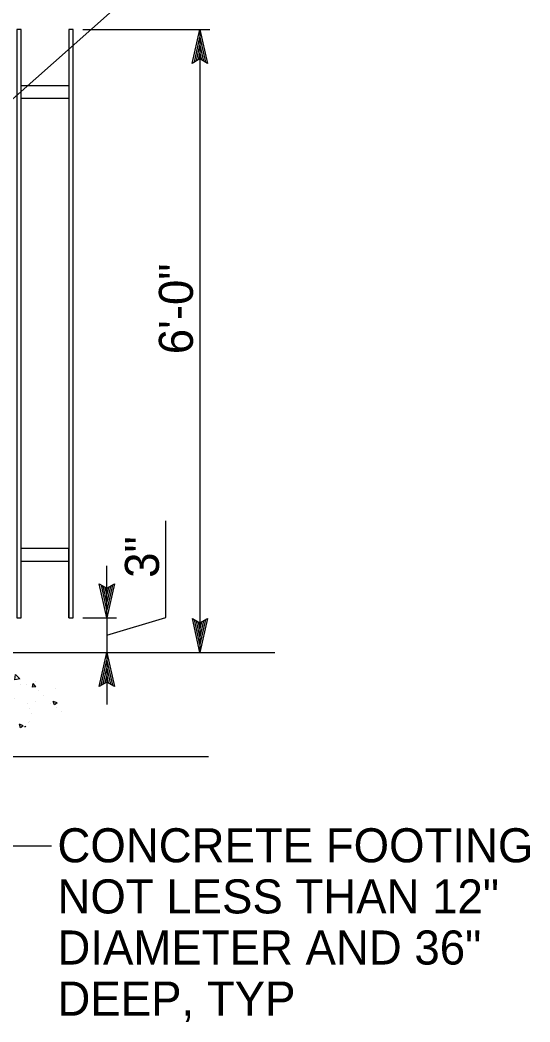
# Model space of a CAD drawing. Extents: x -123486 to -116575, y -107066 to -101122.
# Drawn here: x -118413.2 to -118323.4, y -103122.8 to -102946.3 of the extents above; entities that cross this region are included whole.
import ezdxf

# ---------------------------------------------------------------- set-up
doc = ezdxf.new("R2010")
doc.units = 0
for name, color, linetype in [('Erosion C (Lv35)', 7, 'Continuous'), ('G-MARK', 7, 'Continuous'), ('Misc CnstDet(22)', 7, 'Continuous')]:
    doc.layers.add(name, color=color, linetype=linetype)

# ---------------------------------------------------------------- blocks, each defined once
blk = doc.blocks.new('SC8415')
at = {"layer": 'Erosion C (Lv35)'}
for p, q in [((-1.69606, 1.76963), (-1.69579, 1.76945)), ((-1.69579, 1.76945), (-1.69573, 1.76963)), ((-1.70669, 1.76754), (-1.7059, 1.76836)), ((-1.70579, 1.7674), (-1.7059, 1.76836)), ((-1.70304, 1.76795), (-1.70304, 1.76795)), ((-1.6975, 1.7679), (-1.6975, 1.7679)), ((-1.69662, 1.7688), (-1.69662, 1.7688)), ((-1.69408, 1.76913), (-1.69408, 1.76913)), ((-1.69228, 1.76861), (-1.69228, 1.76861)), ((-1.68716, 1.76862), (-1.68716, 1.76862)), ((-1.68715, 1.76926), (-1.68715, 1.76926)), ((-1.70955, 1.76614), (-1.70906, 1.76672)), ((-1.70955, 1.76614), (-1.70894, 1.76608)), ((-1.70943, 1.76711), (-1.70943, 1.76711)), ((-1.70894, 1.76609), (-1.70906, 1.76672)), ((-1.70791, 1.76649), (-1.70791, 1.76649)), ((-1.70689, 1.76745), (-1.70689, 1.76745)), ((-1.70672, 1.76656), (-1.70672, 1.76656)), ((-1.70669, 1.76754), (-1.70579, 1.7674)), ((-1.70484, 1.76651), (-1.70412, 1.76679)), ((-1.70484, 1.76651), (-1.70433, 1.76617)), ((-1.70433, 1.76617), (-1.70412, 1.76679)), ((-1.70278, 1.76714), (-1.70278, 1.76714)), ((-1.70226, 1.7655), (-1.70177, 1.76608)), ((-1.70165, 1.76545), (-1.70177, 1.76609)), ((-1.7013, 1.76633), (-1.7013, 1.76633)), ((-1.69901, 1.76659), (-1.69901, 1.76659)), ((-1.69588, 1.7661), (-1.69588, 1.7661)), ((-1.69585, 1.76586), (-1.69506, 1.76668)), ((-1.69494, 1.76572), (-1.69506, 1.76668)), ((-1.69309, 1.7676), (-1.69309, 1.7676)), ((-1.69023, 1.7657), (-1.68952, 1.76597)), ((-1.68973, 1.76536), (-1.68952, 1.76597)), ((-1.68649, 1.76648), (-1.68649, 1.76648)), ((-1.68473, 1.76639), (-1.68473, 1.76639)), ((-1.68394, 1.76681), (-1.68394, 1.76681)), ((-1.682, 1.76664), (-1.682, 1.76664)), ((-1.71312, 1.76577), (-1.71312, 1.76577)), ((-1.71086, 1.76455), (-1.71086, 1.76455)), ((-1.71, 1.76543), (-1.71, 1.76543)), ((-1.70494, 1.76557), (-1.70494, 1.76557)), ((-1.70458, 1.7652), (-1.70458, 1.7652)), ((-1.70226, 1.7655), (-1.70165, 1.76545)), ((-1.6993, 1.76479), (-1.6993, 1.76479)), ((-1.69916, 1.76497), (-1.69916, 1.76497)), ((-1.69762, 1.76452), (-1.69762, 1.76452)), ((-1.69675, 1.76513), (-1.69675, 1.76513)), ((-1.69658, 1.76435), (-1.69658, 1.76435)), ((-1.69585, 1.76586), (-1.69494, 1.76572)), ((-1.69497, 1.76486), (-1.69449, 1.76545)), ((-1.69497, 1.76486), (-1.69437, 1.76481)), ((-1.69437, 1.76481), (-1.69448, 1.76545)), ((-1.69373, 1.76474), (-1.69373, 1.76474)), ((-1.6929, 1.76563), (-1.6929, 1.76563)), ((-1.69241, 1.76523), (-1.69241, 1.76523)), ((-1.69065, 1.76537), (-1.69065, 1.76537)), ((-1.69045, 1.76587), (-1.69045, 1.76587)), ((-1.69023, 1.7657), (-1.68973, 1.76536)), ((-1.68831, 1.76451), (-1.68831, 1.76451)), ((-1.68769, 1.76423), (-1.6872, 1.76481)), ((-1.68769, 1.76423), (-1.68708, 1.76417)), ((-1.68727, 1.76588), (-1.68727, 1.76588)), ((-1.68708, 1.76417), (-1.6872, 1.76481)), ((-1.68503, 1.76565), (-1.68503, 1.76565)), ((-1.685, 1.76418), (-1.68421, 1.765)), ((-1.685, 1.76418), (-1.6841, 1.76404)), ((-1.6841, 1.76404), (-1.68421, 1.765)), ((-1.68289, 1.76428), (-1.68289, 1.76428)), ((-1.71337, 1.76324), (-1.71266, 1.76351)), ((-1.71337, 1.76324), (-1.71287, 1.7629)), ((-1.71325, 1.76239), (-1.71325, 1.76239)), ((-1.71287, 1.7629), (-1.71266, 1.76351)), ((-1.7121, 1.7631), (-1.7121, 1.7631)), ((-1.70956, 1.76344), (-1.70956, 1.76344)), ((-1.70803, 1.7631), (-1.70803, 1.7631)), ((-1.70571, 1.76395), (-1.70571, 1.76395)), ((-1.7029, 1.76375), (-1.7029, 1.76375)), ((-1.7025, 1.76334), (-1.7025, 1.76334)), ((-1.69877, 1.76242), (-1.69806, 1.7627)), ((-1.69877, 1.76242), (-1.69827, 1.76208)), ((-1.69826, 1.76208), (-1.69806, 1.7627)), ((-1.68916, 1.76247), (-1.68916, 1.76247)), ((-1.6874, 1.7625), (-1.6874, 1.7625)), ((-1.68662, 1.7628), (-1.68662, 1.7628)), ((-1.68277, 1.76331), (-1.68277, 1.76331)), ((-1.71417, 1.76163), (-1.71417, 1.76163)), ((-1.70874, 1.7614), (-1.70874, 1.7614)), ((-1.70843, 1.76232), (-1.70843, 1.76232)), ((-1.70332, 1.76117), (-1.70332, 1.76117)), ((-1.70197, 1.76078), (-1.70197, 1.76078)), ((-1.69943, 1.76112), (-1.69943, 1.76112)), ((-1.6979, 1.76094), (-1.6979, 1.76094)), ((-1.69775, 1.76113), (-1.69775, 1.76113)), ((-1.69558, 1.76162), (-1.69558, 1.76162)), ((-1.6927, 1.7608), (-1.6927, 1.7608)), ((-1.69253, 1.76185), (-1.69253, 1.76185)), ((-1.69247, 1.76071), (-1.69247, 1.76071)), ((-1.68677, 1.76182), (-1.68677, 1.76182)), ((-1.68417, 1.76161), (-1.68346, 1.76188)), ((-1.68417, 1.76161), (-1.68366, 1.76127)), ((-1.68366, 1.76127), (-1.68346, 1.76188)), ((-1.70839, 1.75994), (-1.70839, 1.75994)), ((-1.70815, 1.75972), (-1.70815, 1.75972)), ((-1.70775, 1.75896), (-1.70765, 1.75908)), ((-1.70762, 1.7589), (-1.70765, 1.75908)), ((-1.70731, 1.75915), (-1.7066, 1.75942)), ((-1.70731, 1.75915), (-1.7068, 1.75881)), ((-1.7068, 1.75881), (-1.7066, 1.75942)), ((-1.70455, 1.75876), (-1.70455, 1.75876)), ((-1.70302, 1.76037), (-1.70302, 1.76037)), ((-1.69862, 1.75978), (-1.69862, 1.75978)), ((-1.68929, 1.7588), (-1.68929, 1.7588)), ((-1.68752, 1.75912), (-1.68752, 1.75912)), ((-1.68705, 1.76048), (-1.68705, 1.76048)), ((-1.68544, 1.7593), (-1.68544, 1.7593)), ((-1.68224, 1.75988), (-1.68224, 1.75988)), ((-1.70085, 1.75786), (-1.70036, 1.75844)), ((-1.70085, 1.75786), (-1.70025, 1.7578)), ((-1.70024, 1.75781), (-1.70036, 1.75844)), ((-1.69825, 1.75762), (-1.69825, 1.75762)), ((-1.69787, 1.75775), (-1.69787, 1.75775)), ((-1.69357, 1.75722), (-1.69308, 1.7578)), ((-1.69357, 1.75722), (-1.69296, 1.75717)), ((-1.69296, 1.75717), (-1.69307, 1.75781)), ((-1.69271, 1.75833), (-1.692, 1.75861)), ((-1.69271, 1.75833), (-1.6922, 1.75799)), ((-1.69265, 1.75847), (-1.69265, 1.75847)), ((-1.6922, 1.75799), (-1.69199, 1.75861)), ((-1.69183, 1.75846), (-1.69183, 1.75846)), ((-1.68628, 1.75658), (-1.68579, 1.75717)), ((-1.68567, 1.75653), (-1.68579, 1.75717)), ((-1.68628, 1.75658), (-1.68567, 1.75653))]:
    blk.add_line(p, q, dxfattribs=at)

msp = doc.modelspace()

# ---------------------------------------------------------------- linework, layer by layer
at = {"layer": 'G-MARK'}
for p, q in [((-118452.21, -102993.76), (-118367.63, -102918.62)), ((-118402.1, -102947.98), (-118379.76, -102947.98)), ((-118382.82, -102953.98), (-118381.48, -102947.98)), ((-118381.48, -102947.98), (-118381.48, -103057.71)), ((-118381.48, -102947.98), (-118381.48, -102947.98)), ((-118381.48, -102947.98), (-118380.15, -102953.98)), ((-118382.46, -102953.76), (-118381.48, -102949.36)), ((-118382.1, -102953.53), (-118381.48, -102950.74)), ((-118381.48, -102950.74), (-118380.85, -102953.57)), ((-118381.47, -102949.37), (-118380.5, -102953.75)), ((-118381.75, -102953.35), (-118381.48, -102952.13)), ((-118381.48, -102952.13), (-118381.21, -102953.33)), ((-118381.48, -102953.18), (-118382.82, -102953.98)), ((-118382.82, -102953.98), (-118382.82, -102953.98)), ((-118380.15, -102953.98), (-118381.48, -102953.18)), ((-118380.15, -102953.98), (-118380.15, -102953.98)), ((-118387.46, -103051.54), (-118387.46, -103034.54)), ((-118397.87, -103051.61), (-118397.87, -103042.47)), ((-118397.87, -103051.61), (-118399.2, -103045.61)), ((-118399.2, -103045.61), (-118399.2, -103045.61)), ((-118399.2, -103045.61), (-118397.87, -103046.41)), ((-118397.87, -103051.61), (-118399.2, -103045.61)), ((-118399.2, -103045.61), (-118399.2, -103045.61)), ((-118399.2, -103045.61), (-118397.87, -103046.41)), ((-118397.87, -103050.22), (-118398.84, -103045.85)), ((-118397.87, -103050.22), (-118398.84, -103045.85)), ((-118397.87, -103048.85), (-118398.49, -103046.03)), ((-118397.87, -103048.85), (-118398.49, -103046.03)), ((-118397.87, -103046.41), (-118396.53, -103045.61)), ((-118396.53, -103045.61), (-118397.87, -103051.61)), ((-118397.87, -103046.41), (-118396.53, -103045.61)), ((-118396.53, -103045.61), (-118397.87, -103051.61)), ((-118396.89, -103045.83), (-118397.87, -103050.23)), ((-118396.89, -103045.83), (-118397.87, -103050.23)), ((-118397.25, -103046.06), (-118397.87, -103048.85)), ((-118397.25, -103046.06), (-118397.87, -103048.85)), ((-118396.53, -103045.61), (-118396.53, -103045.61)), ((-118396.53, -103045.61), (-118396.53, -103045.61)), ((-118397.87, -103047.47), (-118398.14, -103046.26)), ((-118397.87, -103047.47), (-118398.14, -103046.26)), ((-118397.59, -103046.24), (-118397.87, -103047.47)), ((-118397.59, -103046.24), (-118397.87, -103047.47)), ((-118402.1, -103051.61), (-118396.16, -103051.61)), ((-118397.87, -103054.66), (-118387.46, -103051.54)), ((-118397.87, -103051.61), (-118397.87, -103057.71)), ((-118397.87, -103051.61), (-118397.87, -103057.71)), ((-118397.87, -103051.61), (-118397.87, -103051.61)), ((-118397.87, -103051.61), (-118397.87, -103051.61)), ((-118381.48, -103057.71), (-118382.81, -103051.71)), ((-118382.81, -103051.71), (-118382.81, -103051.71)), ((-118382.81, -103051.71), (-118381.48, -103052.51)), ((-118381.48, -103057.71), (-118382.81, -103051.71)), ((-118382.81, -103051.71), (-118382.81, -103051.71)), ((-118382.81, -103051.71), (-118381.48, -103052.51)), ((-118381.48, -103056.32), (-118382.45, -103051.94)), ((-118381.48, -103056.32), (-118382.45, -103051.94)), ((-118381.47, -103054.95), (-118382.1, -103052.12)), ((-118381.47, -103054.95), (-118382.1, -103052.12)), ((-118381.47, -103053.57), (-118381.74, -103052.36)), ((-118381.47, -103053.57), (-118381.74, -103052.36)), ((-118381.48, -103052.51), (-118380.14, -103051.71)), ((-118380.14, -103051.71), (-118381.48, -103057.71)), ((-118381.48, -103052.51), (-118380.14, -103051.71)), ((-118380.14, -103051.71), (-118381.48, -103057.71)), ((-118380.49, -103051.93), (-118381.47, -103056.33)), ((-118380.49, -103051.93), (-118381.47, -103056.33)), ((-118380.85, -103052.16), (-118381.47, -103054.95)), ((-118380.85, -103052.16), (-118381.47, -103054.95)), ((-118381.2, -103052.34), (-118381.47, -103053.57)), ((-118381.2, -103052.34), (-118381.47, -103053.57)), ((-118380.14, -103051.71), (-118380.14, -103051.71)), ((-118380.14, -103051.71), (-118380.14, -103051.71)), ((-118399.21, -103063.71), (-118397.87, -103057.71)), ((-118399.21, -103063.71), (-118397.87, -103057.71)), ((-118397.87, -103057.71), (-118397.87, -103066.85)), ((-118397.87, -103057.71), (-118397.87, -103057.71)), ((-118397.87, -103057.71), (-118396.54, -103063.71)), ((-118397.87, -103057.71), (-118397.87, -103057.71)), ((-118397.87, -103057.71), (-118396.54, -103063.71)), ((-118381.48, -103057.71), (-118381.48, -103057.71)), ((-118381.48, -103057.71), (-118381.48, -103057.71)), ((-118398.85, -103063.49), (-118397.87, -103059.09)), ((-118398.85, -103063.49), (-118397.87, -103059.09)), ((-118397.87, -103059.1), (-118396.9, -103063.47)), ((-118397.87, -103059.1), (-118396.9, -103063.47)), ((-118398.5, -103063.26), (-118397.87, -103060.47)), ((-118398.5, -103063.26), (-118397.87, -103060.47)), ((-118398.15, -103063.08), (-118397.87, -103061.85)), ((-118398.15, -103063.08), (-118397.87, -103061.85)), ((-118397.87, -103060.47), (-118397.25, -103063.3)), ((-118397.87, -103060.47), (-118397.25, -103063.3)), ((-118397.87, -103061.85), (-118397.61, -103063.06)), ((-118397.87, -103061.85), (-118397.61, -103063.06)), ((-118397.87, -103062.91), (-118399.21, -103063.71)), ((-118397.87, -103062.91), (-118399.21, -103063.71)), ((-118399.21, -103063.71), (-118399.21, -103063.71)), ((-118399.21, -103063.71), (-118399.21, -103063.71)), ((-118396.54, -103063.71), (-118397.87, -103062.91)), ((-118396.54, -103063.71), (-118397.87, -103062.91)), ((-118396.54, -103063.71), (-118396.54, -103063.71)), ((-118396.54, -103063.71), (-118396.54, -103063.71)), ((-118407.59, -103091.83), (-118418.39, -103091.83))]:
    msp.add_line(p, q, dxfattribs=at)
at = {"layer": 'Misc CnstDet(22)'}
for p, q in [((-118403.82, -102947.98), (-118403.82, -102947.98)), ((-118382.82, -102953.98), (-118381.48, -102947.98)), ((-118381.48, -102947.98), (-118381.48, -102947.98)), ((-118381.48, -102947.98), (-118380.15, -102953.98)), ((-118382.46, -102953.76), (-118381.48, -102949.36)), ((-118382.1, -102953.53), (-118381.48, -102950.74)), ((-118381.48, -102950.74), (-118380.85, -102953.57)), ((-118381.47, -102949.37), (-118380.5, -102953.75)), ((-118381.75, -102953.35), (-118381.48, -102952.13)), ((-118381.48, -102952.13), (-118381.21, -102953.33)), ((-118381.48, -102953.18), (-118382.82, -102953.98)), ((-118382.82, -102953.98), (-118382.82, -102953.98)), ((-118380.15, -102953.98), (-118381.48, -102953.18)), ((-118380.15, -102953.98), (-118380.15, -102953.98)), ((-118404.58, -102957.89), (-118412.96, -102957.89)), ((-118404.58, -102960.17), (-118412.96, -102960.17)), ((-118404.58, -103039.42), (-118412.96, -103039.42)), ((-118404.58, -103051.61), (-118404.58, -103039.42)), ((-118404.58, -103041.71), (-118412.96, -103041.71)), ((-118403.82, -103051.61), (-118403.82, -103051.61)), ((-118444.68, -103057.71), (-118368.28, -103057.71)), ((-118403.82, -103057.71), (-118403.82, -103057.71)), ((-118403.82, -103057.71), (-118403.82, -103057.71)), ((-118402.1, -103057.71), (-118379.76, -103057.71)), ((-118402.1, -103057.71), (-118396.16, -103057.71)), ((-118397.87, -103057.71), (-118397.87, -103057.71)), ((-118381.48, -103057.71), (-118381.48, -103057.71)), ((-118444.68, -103076), (-118379.99, -103076))]:
    msp.add_line(p, q, dxfattribs=at)
for points in [[(-118413.73, -103051.61), (-118412.96, -103051.61), (-118412.96, -102947.98), (-118413.73, -102947.98)], [(-118404.58, -103051.61), (-118403.82, -103051.61), (-118403.82, -102947.98), (-118404.58, -102947.98)]]:
    msp.add_lwpolyline(points, close=True, dxfattribs=at)

# ---------------------------------------------------------------- block references
at = {"layer": 'Misc CnstDet(22)', "xscale": 984.251968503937, "yscale": -984.251968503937, "rotation": 180}
msp.add_blockref('SC8415', (-120093, -104802.07), dxfattribs=at)

# ---------------------------------------------------------------- texts
at = {"layer": 'Misc CnstDet(22)'}
for s, p in [('6\'-0"', (-118382.71, -103005.18)), ('3"', (-118388.69, -103044.56))]:
    msp.add_text(s, height=6, rotation=90, dxfattribs=at).set_placement(p)
for s, p in [('CONCRETE FOOTING', (-118406.57, -103094.67)), ('NOT LESS THAN 12"', (-118406.57, -103103.67)), ('DIAMETER AND 36"', (-118406.57, -103112.67)), ('DEEP, TYP', (-118406.57, -103121.67))]:
    msp.add_text(s, height=6, dxfattribs=at).set_placement(p)

doc.saveas('drawing.dxf')
